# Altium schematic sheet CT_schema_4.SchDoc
size 293 x 156 mm
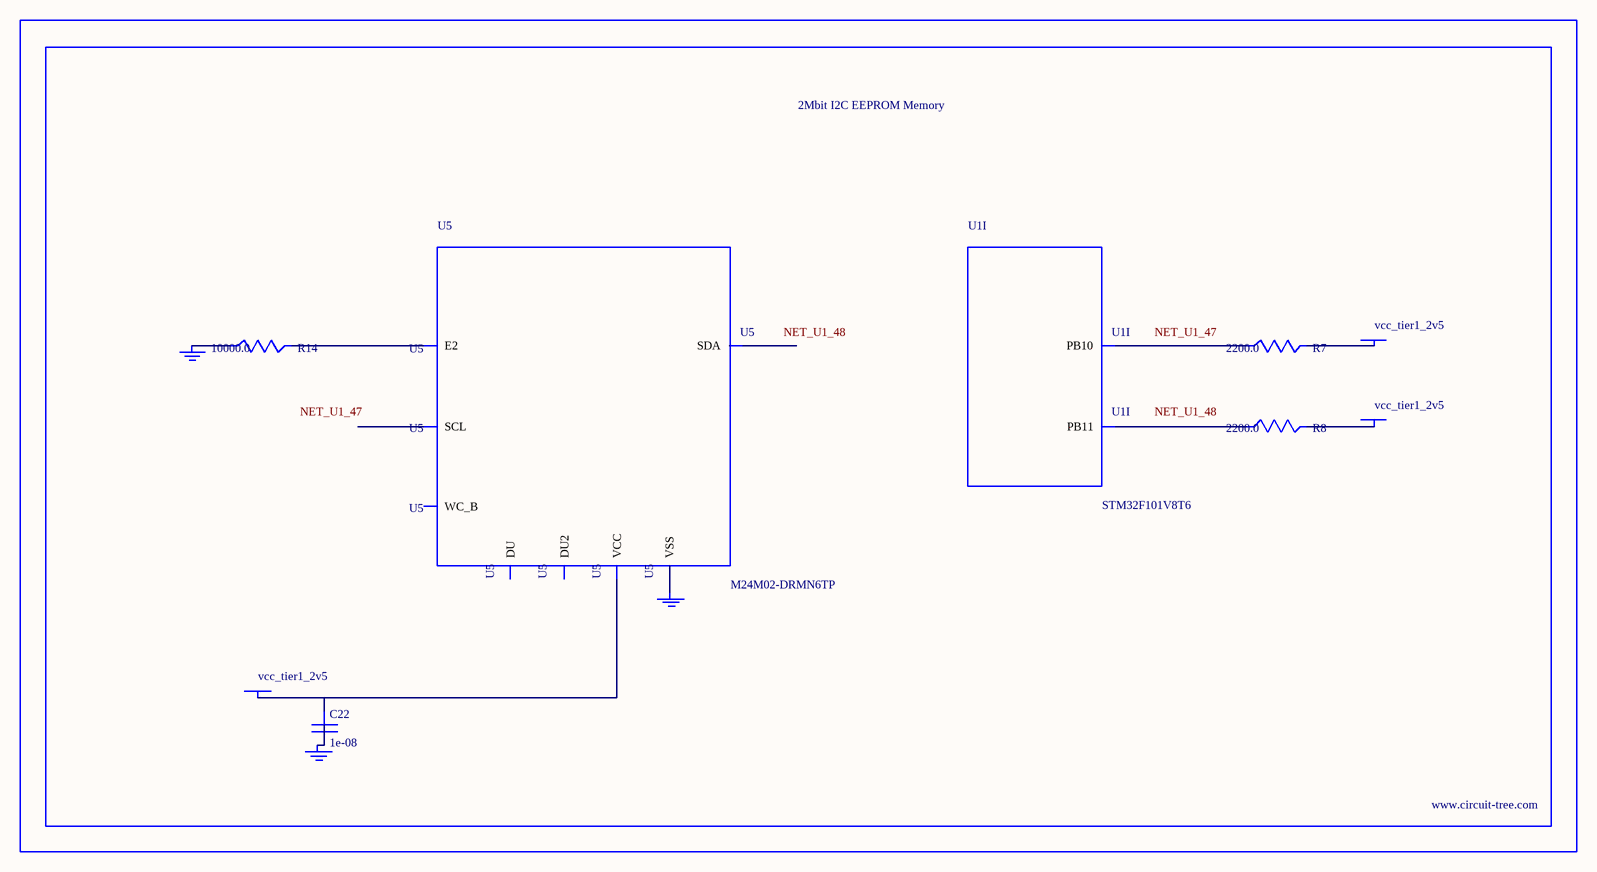
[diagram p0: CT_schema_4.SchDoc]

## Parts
BORDER3  (no value)
C22  1e-08  [C0402]
GND_INSTANCE_3_0  (no value)
GND_INSTANCE_3_1  (no value)
GND_INSTANCE_3_2  (no value)
POWER_INSTANCE_3_0  vcc_tier1_2v5
POWER_INSTANCE_3_1  vcc_tier1_2v5
POWER_INSTANCE_3_2  vcc_tier1_2v5
R7  2200.0  [R0603]
R8  2200.0  [R0603]
R14  10000.0  [R0603]
U1  STM32F101V8T6  [LQFP100]  (part I of 10)
U5  M24M02-DRMN6TP  [SOIC-8]

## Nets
NetC22_1: C22.1 POWER_INSTANCE_3_0.0(PWR) U5.8(VCC)
NetC22_2: C22.2 GND_INSTANCE_3_1.0(GND)
NetGND_INSTANCE_3_0_0: GND_INSTANCE_3_0.0(GND) R14.1
NetGND_INSTANCE_3_2_0: GND_INSTANCE_3_2.0(GND) U5.4(VSS)
NetPOWER_INSTANCE_3_1_0: POWER_INSTANCE_3_1.0(PWR) R7.2
NetPOWER_INSTANCE_3_2_0: POWER_INSTANCE_3_2.0(PWR) R8.2
NetR7_1: R7.1 U1.47(PB10)
NetR8_1: R8.1 U1.48(PB11)
NetR14_2: R14.2 U5.3(E2)

Not connected (* = marked no-connect by the designer): U5 1(DU) 2(DU2) 5(SDA) 6(SCL) 7(WC_B)

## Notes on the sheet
- Labels drawn without touching a wire or pin: NET_U1_47, NET_U1_48

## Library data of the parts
BORDER3 = BORDER_PAGE3
C22 = C0402C103K3RAC
GND_INSTANCE_3_0-GND_INSTANCE_3_2 = GND
POWER_INSTANCE_3_0-POWER_INSTANCE_3_2 = PWR
R7 R8 = RC0603JR-072K2L
R14 = RC0603JR-0710KL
